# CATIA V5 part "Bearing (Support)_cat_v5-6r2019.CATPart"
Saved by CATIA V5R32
Part number: Bearing (Support)
Bounding box of the stored display mesh (mm): x -270 to 10, y -39.842 to 39.842, z -34.808 to 139.842
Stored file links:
  D:\PROJECTS\Project 2022\CATIA V5 6R 2022\Resources\Tutorial Files\c16_catia_v5_6r2022_tut\CV joint\Bearing (Support)_cat_v5-6r2019.CATPart
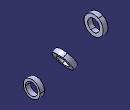
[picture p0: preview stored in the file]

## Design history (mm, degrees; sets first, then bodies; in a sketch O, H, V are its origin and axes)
Body1 (main body)
  Sketch1 on yz-plane, origin (0, 0, 0), H (0, 1, 0), V (0, 0, 1)
    circle A1 centre (0, 0) radius 25
    circle A2 centre (0, 0) radius 35
    radius A1 = 25
    radius A2 = 35
  Pad1: profile Sketch1, direction (1, 0, 0), length 10, mirrored extent
  Sketch2 on zx-plane, origin (0, 0, 0), H (-1, 0, 0), V (0, 0, 1)
    construction line L1 (0, 0) -> (60, 0)
    construction line L2 (60, 0) -> (194.1972, 77.4788)
    line L3 (107.5, 56.2917) -> (124.8205, 66.2917)
    line L4 (124.8205, 66.2917) -> (117.3205, 79.282)
    line L5 (117.3205, 79.282) -> (100, 69.282)
    point P6 (100, 69.282)
    line L6 (100, 69.282) -> (107.5, 56.2917)
    angle L2 L1 = 30
    distance L6 L4 = 20
    length L6 = 15
    distance L3 L2 = 25
    distance P6 V = 100
    length L1 = 60
    horizontal: L1 H
    perpendicularity: L4 L3
    parallelism: L5 L2, L6 L4
  Sketch3 on zx-plane, origin (0, 0, 0), H (-1, 0, 0), V (0, 0, 1)
    line L1 (60, 0) -> (221.9169, 93.4828)
    point P1 (60, 0)
    reference projected line E1 (107.5, 56.2917) -> (124.8205, 66.2917) from Sketch2.L3
    reference projected line E2 (107.5, 56.2917) -> (124.8205, 66.2917) from Sketch2.L3
    distance E2 L1 = 25
    coincidence: P1 H
    parallelism: L1 E1
  Shaft1: profile Sketch2, axis Sketch3.L1, angle 360
  Sketch4 on zx-plane, origin (0, 0, 0), H (-1, 0, 0), V (0, 0, 1)
    construction line L1 (188.3301, 100) -> (395.6544, 100)
    point P3 (260, 132.5)
    line L2 (270, 140) -> (270, 125)
    line L3 (270, 125) -> (250, 125)
    line L4 (250, 125) -> (250, 140)
    line L5 (250, 140) -> (270, 140)
    distance L1 H = 100
    length L5 = 20
    length L4 = 15
    distance L1 L3 = 25
    distance L4 V = 250
    horizontal: L1 H, L3 H, L5 H
    vertical: L2 V, L4 V
    equidistance: L2 L4 P3, L3 L5 P3
  Sketch5 on zx-plane, origin (0, 0, 0), H (-1, 0, 0), V (0, 0, 1)
    line L1 (210.3804, 100) -> (348.9415, 100)
    reference projected line E1 (250, 125) -> (270, 125) from Sketch4.L3
    distance L1 E1 = 25
    horizontal: L1 H
  Shaft2: profile Sketch4, axis Sketch5.L1, angle 360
